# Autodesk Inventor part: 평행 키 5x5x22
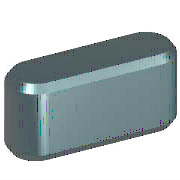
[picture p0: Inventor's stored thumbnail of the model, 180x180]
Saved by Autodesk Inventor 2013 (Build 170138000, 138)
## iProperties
IsCustomPart: 1
Created: 2012-02
Part Number: 평행 키 5x5x22
Material: 강철, 연강
Description: 평행 키
Document SubType Name: Modeling
Standard: JIS B 1301
Designer: mdu-01
Standards Organization: JIS
Language: ko-KR
Size Designation: 5x5x22
Categories: <MemberInstance><Categories><Category DisplayName="샤프트 부품" InternalName="7f7aeb1f-a693-4053-b835-cee3144e0d98" Mnemonic="SHFT"><Category DisplayName="키" Interna
Density: 1 g/cm^3
Author: mdu-01
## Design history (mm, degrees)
workplane "Work Plane1"
workplane "Work Plane2"
sketch "스케치1"
  geometry: L1 (2.5, 2.5)-(19.5, 2.5); L2 (19.5, -2.5)-(2.5, -2.5); L3 (0, 9.4)-(0, -7.4) reference; L4 (-5, 0)-(30, 0) reference; L5 (22, 0)-(22, 7); A1 r 2.5 centre (2.5, 0) between (2.5, 2.5) and (2.5, -2.5); A2 r 2.5 centre (19.5, 0) between (19.5, -2.5) and (19.5, 2.5)
  constraints: 6 end point, 5 point on circle, 4 tangent, 3 point on line, 2 centre point, 1 horizontal, 1 parallel, 1 perpendicular
  dimensions: "d0" = 2.5 radius of A1 (= 0.5 x PB); "d13" = 2.5 radius of A2 (= 0.5 x PB); "d14" = 22 distance between parallel lines of L5 L3 (= NLG)
extrude "본체1" new body sketch "스케치1" taper "d3" = 0 deg; stored distance "d4" = 10
workplane "Work Plane3"
body "Solid1"
chamfer "모따기1" distance "d8" = 0.4 (= PHH); stored, may be unused: second distance "d9" = 0.4 (= PHH), angle "d15" = 45 deg
other parameters: "d1" = -3 (= -PNT), "d2" = 2 (= PH - PNT), "NLG" = 22 [user parameter; used in 3 equation terms], "PB" = 5 [user parameter; used in 2 equation terms], "PNT" = 3 [user parameter; used in 2 equation terms], "PH" = 5 [user parameter; used in 1 equation term], "PHH" = 0.4 [user parameter; used in 2 equation terms], "d10" = 0, "d16" = 0, "d17" = 0, "d18" = 0, "WDMIN" = 12 [user parameter], "PLB2" = 22 (= NLG) [user parameter], "WDMAX" = 17 [user parameter], "PLB1" = 22 (= NLG) [user parameter], "RR" = 0.16 [user parameter], "PUEB" = 2.3 [user parameter]
